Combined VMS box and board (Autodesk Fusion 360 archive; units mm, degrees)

design "Combined VMS" references "VMS Control box", "VMS"
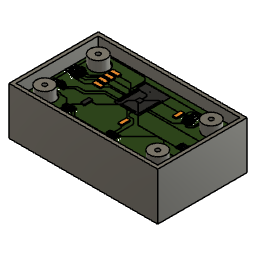
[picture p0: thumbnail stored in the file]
component_insert "Component Insert1"
component_insert "Component Insert2"

design "VMS"
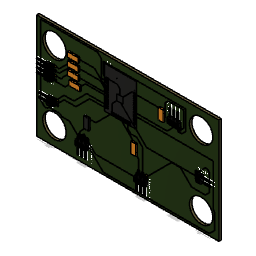
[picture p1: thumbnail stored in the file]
sketch "Outline" plane through (0, 0, 0) normal (0, 0, 1) x axis (1, 0, 0)
  line L1 (118, 0) -> (0, 0)
  line L2 (118, 68) -> (118, 0)
  line L3 (0, 68) -> (118, 68)
  line L4 (0, 0) -> (0, 68)
canvas "Canvas1" bodies "Board"
canvas "Canvas2" bodies "Board"
pcbhole "PCBHole1" HoleDepth 1.605 HoleDiameter 15.142 TipAngle 10313.2
pcbhole "PCBHole2" HoleDepth 1.605 HoleDiameter 15.142 TipAngle 10313.2
pcbhole "PCBHole3" HoleDepth 1.605 HoleDiameter 15.142 TipAngle 10313.2
pcbhole "PCBHole4" HoleDepth 1.605 HoleDiameter 15.142 TipAngle 10313.2
pcbhole "PCBHole5" HoleDepth 1.605 HoleDiameter 0.35 TipAngle 10313.2
pcbhole "PCBHole6" HoleDepth 1.605 HoleDiameter 0.35 TipAngle 10313.2
pcbhole "PCBHole7" HoleDepth 1.605 HoleDiameter 0.35 TipAngle 10313.2
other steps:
base_feature "Base Feature1"
base_feature "Base Feature1"
box_primitive "BoxPrimitive1" DistanceX 7.0612 DistanceY 3.2004 DistanceZ 1 OffsetDistanceX 0 OffsetDistanceY 0
pcbextrude "PCBExtrude1"
pcbextrude "PCBExtrude1"
base_feature "Base Feature1"
box_primitive "BoxPrimitive1" DistanceX 20.69 DistanceY 26.905 DistanceZ 0.1 OffsetDistanceX 0 OffsetDistanceY 0
extrude "Extrude1" sketch "Outline" blind 1.5 bodies "Board"
pcbextrude "PCBExtrude1"
pcbextrude "PCBExtrude1"
pcbhole "PCBHole1" HoleDepth 1.606 HoleDiameter 15.142 TipAngle 10313.2
pcbhole "PCBHole1" HoleDepth 1.606 HoleDiameter 15.142 TipAngle 10313.2
pcbhole "PCBHole2" HoleDepth 1.606 HoleDiameter 15.142 TipAngle 10313.2
pcbhole "PCBHole2" HoleDepth 1.606 HoleDiameter 15.142 TipAngle 10313.2
pcbhole "PCBHole3" HoleDepth 1.606 HoleDiameter 15.142 TipAngle 10313.2
pcbhole "PCBHole3" HoleDepth 1.606 HoleDiameter 15.142 TipAngle 10313.2
pcbhole "PCBHole4" HoleDepth 1.606 HoleDiameter 15.142 TipAngle 10313.2
pcbhole "PCBHole4" HoleDepth 1.606 HoleDiameter 15.142 TipAngle 10313.2
pcbhole "PCBHole5" HoleDepth 1.606 HoleDiameter 0.35 TipAngle 10313.2
pcbhole "PCBHole5" HoleDepth 1.606 HoleDiameter 0.35 TipAngle 10313.2
pcbhole "PCBHole6" HoleDepth 1.606 HoleDiameter 0.35 TipAngle 10313.2
pcbhole "PCBHole6" HoleDepth 1.606 HoleDiameter 0.35 TipAngle 10313.2
pcbhole "PCBHole7" HoleDepth 1.606 HoleDiameter 0.35 TipAngle 10313.2
pcbhole "PCBHole7" HoleDepth 1.606 HoleDiameter 0.35 TipAngle 10313.2
pcbextrude "PCBExtrude1"
pcbextrude "PCBExtrude2" bodies "CopperHoles"
create_component "CreateComponent1"
create_component "CreateComponent2"
create_component "CreateComponent3"
create_component "CreateComponent4"
create_component "CreateComponent5"
create_component "CreateComponent6"
as_built_joint "As-built1"
create_component "CreateComponent3"
create_component "CreateComponent4"
create_component "CreateComponent9"
create_component "CreateComponent10"
create_component "CreateComponent11"
named bodies: "Board", "CopperHoles"

design "VMS Control box"
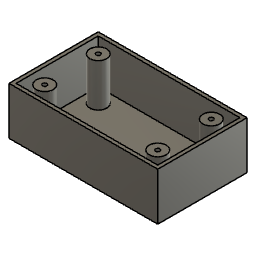
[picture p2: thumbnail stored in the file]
sketch "Sketch1" plane through (0, 0, 0) normal (0, 1, 0) x axis (1, 0, 0)
  line L1 (75, 25) -> (-50, 25)
  line L2 (75, -50) -> (75, 25)
  line L3 (-50, -50) -> (75, -50)
  line L4 (-50, 25) -> (-50, -50)
  horizontal L1
  vertical L2
  horizontal L3
  vertical L4
extrude "Extrude1" new body sketch "Sketch1" along normal blind 40
shell "Shell1" innerThickness 3
cylinder_primitive "CylinderPrimitive1" Height 36 Diameter 14.142
hole "Hole2" HoleDepth 10 HoleDiameter 3.6 TipAngle 180
rectangular_pattern "R-Pattern1" uSpaceDistance 95 vSpaceDistance 45
hole "Hole3" HoleDepth 10 HoleDiameter 3.6 TipAngle 180
hole "Hole4" HoleDepth 10 HoleDiameter 3.6 TipAngle 180
hole "Hole5" HoleDepth 10 HoleDiameter 3.6 TipAngle 180
work_plane "WorkPlane1" AlongDistance 6
sketch "Sketch5" plane through (12.5, 9, 12.5) normal (0, 1, 0) x axis (1, 0, 0)
  line L1 (59.5, -34.5) -> (-59.5, -34.5)
  line L2 (59.5, 34.5) -> (59.5, -34.5)
  line L3 (-59.5, 34.5) -> (59.5, 34.5)
  line L4 (-59.5, -34.5) -> (-59.5, 34.5)
  circle C1 centre (-47.5, 22.5) radius 1.8
  circle C2 centre (-47.5, 22.5) radius 7.071
  circle C3 centre (-47.5, -22.5) radius 7.071
  circle C4 centre (47.5, -22.5) radius 1.8
  circle C5 centre (47.5, -22.5) radius 7.071
  circle C6 centre (47.5, 22.5) radius 7.071
extrude "Extrude1" new body sketch "Sketch5" profile of L1 L2 L3 L4 C2 C3 C5 C6 along normal blind 2
offset_faces "OffsetFaces1" distance -0.5
remove_body "RemoveBody1"
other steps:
create_component "CreateComponent1"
